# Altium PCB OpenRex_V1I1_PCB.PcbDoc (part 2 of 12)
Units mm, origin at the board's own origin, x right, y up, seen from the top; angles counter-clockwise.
Board outline 70 x 95 mm, 10 copper layers (L1, L2, L3, L4 (PWR), L5 (PWR), L6 (PWR), L7 (PWR), L8, L9, L10), stack 1.632 mm thick; 1080 components, 708 nets, 3831 pads, 2373 vias.
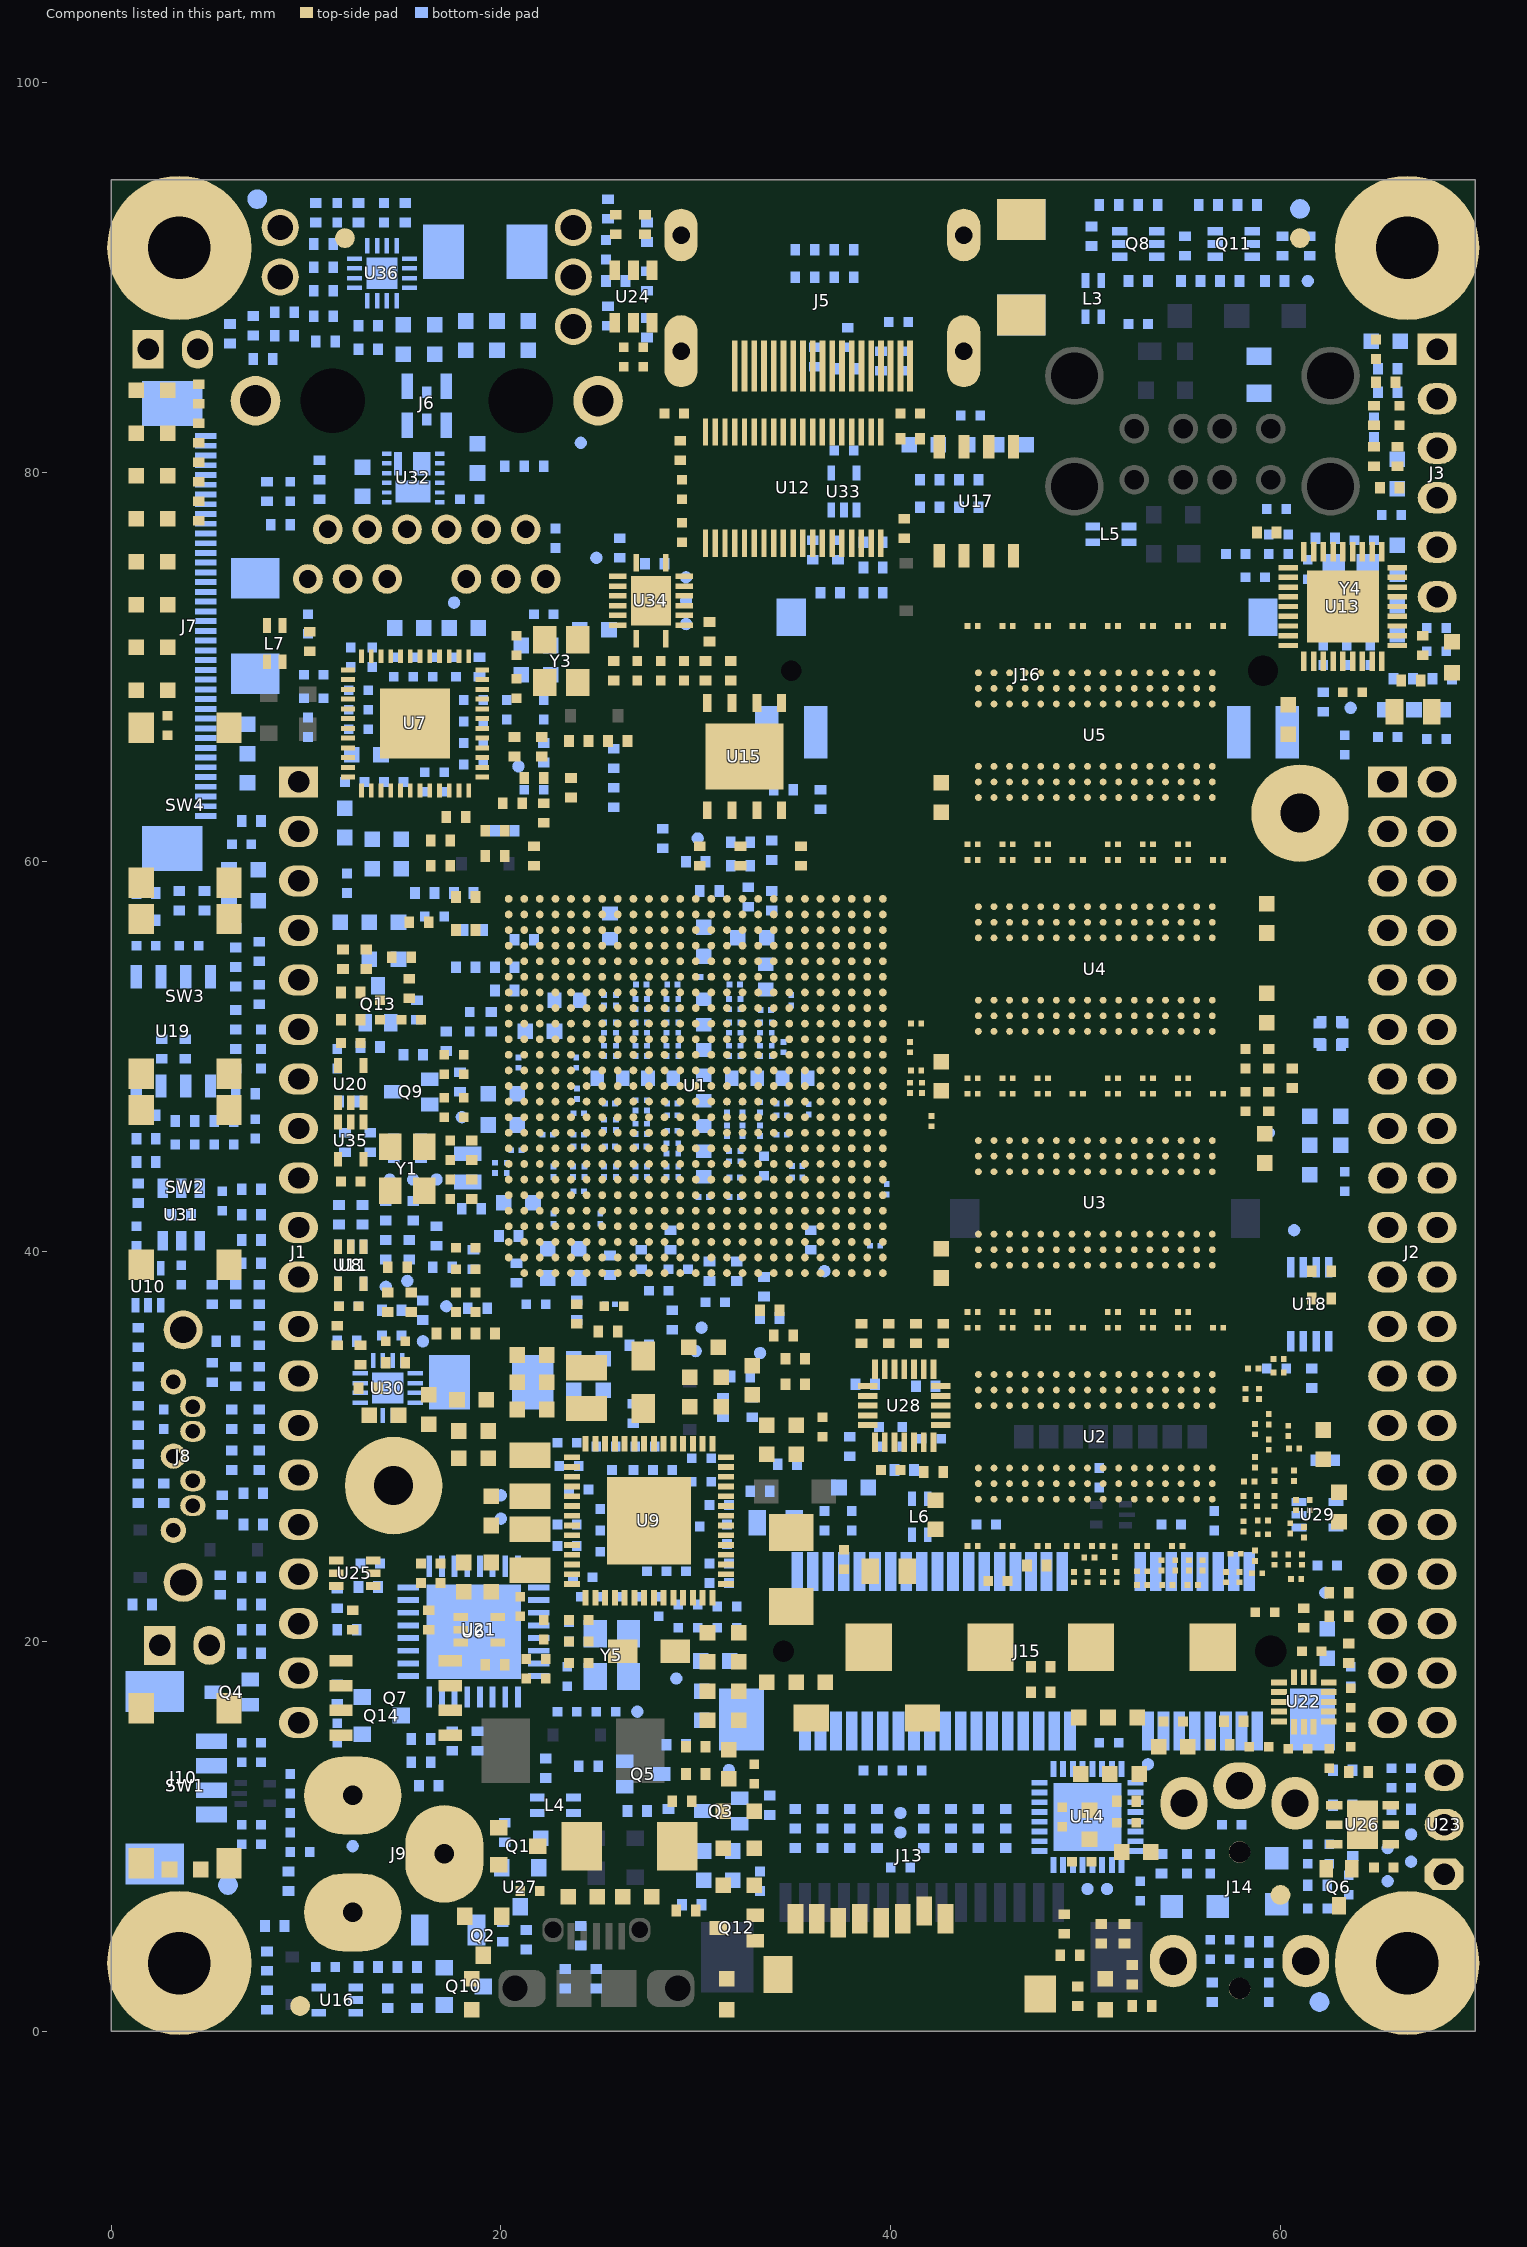
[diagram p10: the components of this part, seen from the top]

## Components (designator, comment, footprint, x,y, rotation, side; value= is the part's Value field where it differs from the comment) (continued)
L7 "ACM2012-900-2P-T002" ACM2012 8.4,71.2 r90 top
L8 "1u / 2.6A" IFSC_79MILX98MIL 24.4,33 r270 top
L9 "1u / 2.6A" IFSC_79MILX98MIL 21.5,28.5 r90 top
L10 "1u / 2.6A" IFSC_79MILX98MIL 21.5,24.7 r270 top
L11 "2u2 / 2.75A" IHLP_160MILX175MIL 34.9,23.7 r90 top
L12 "1u" IHLP_204MILX216MIL 19.5,33.3 r0 bottom locked
L13 "1u" IHLP_204MILX216MIL 19.2,91.3 r0 bottom
MH1 "MH_7.4MMC_3.2MMD" MH_7.4MMD_3.2MMD 3.5,3.5 r0 top locked
MH2 "MH_7.4MMC_3.2MMD" MH_7.4MMD_3.2MMD 66.5,3.5 r0 top locked
MH3 "MH_7.4MMC_3.2MMD" MH_7.4MMD_3.2MMD 66.5,91.5 r0 top locked
MH4 "MH_7.4MMC_3.2MMD" MH_7.4MMD_3.2MMD 3.5,91.5 r0 top locked
MH5 "MH_5MMC_2MMD" MH_5MMD_2MMD 14.5,28 r0 top locked
MH6 "MH_5MMC_2MMD" MH_5MMD_2MMD 61,62.5 r0 top locked
Q1 "DMP2035U-7" SOT-23-3-123 20.9,9.5 r0 top
Q2 "DMP2035U-7" SOT-23-3-123 19.1,4.9 r270 top
Q3 "2N7002BKW,115" SC70_SOT323 31.3,11.3 r180 bottom
Q4 "2N7002BKW,115" SC70_SOT323 6.2,17.4 r180 bottom
Q5 "2N7002BKW,115" SC70_SOT323 27.3,13.2 r0 bottom
Q6 "2N7002BKW,115" SC70_SOT323 63,7.4 r270 top
Q7 "SI4425BDY-T1-E3" 8_SOIC_3.9MM 14.6,17.1 r0 top
Q8 "2N7002BKS,115" SOT363 52.7,91.7 r0 bottom
Q9 "2N7002BKW,115" SC70_SOT323 15.4,48.2 r180 bottom
Q10 "MMBT3906,215" SOT-23-3-123 18.1,2.3 r0 bottom
Q11 "2N7002BKS,115" SOT363 57.6,91.7 r0 bottom
Q12 "2N7002BKW,115" SC70_SOT323 32.1,5.3 r180 top
Q13 "2N7002BKW,115" SC70_SOT323 13.7,52.7 r90 bottom
Q14 "MMBT3906,215" SOT-23-3-123 13.9,16.2 r0 bottom
R1 "47R" R0201 60.4,24.2 r270 top
R2 "47R" R0201 57.9,23.3 r90 top
R3 "47R" R0201 60.7,28.5 r270 top
R4 "240R" R0201 49.6,36.1 r0 top
R5 "240R" R0201 49.6,48.1 r0 top
R6 "10k" R0201 35.8,47.3 r90 bottom
R7 "10k" R0201 39.8,43.2 r270 bottom
R8 "240R" R0201 49.6,60.1 r0 top
R9 "240R" R0201 49.6,72.1 r0 top
R10 "240R" R0201 41.3,51.7 r0 top
R11 "47R" R0201 56,23.9 r270 top
R12 "47R" R0201 59.7,28.5 r270 top
R13 "0R" R0402 23.9,37 r90 bottom
R14 "0R" R0402 20.4,40.8 r0 bottom
R15 "10k" R0402 32.3,61 r0 bottom
R16 "49R9" R0402 19.2,35.8 r180 top
R17 "49R9" R0402 17.2,35.8 r0 top
R18 "0R" R0402 25.6,39.3 r90 bottom
R19 "0R" R0402 19.5,51.8 r270 bottom
R20 "2M2" R0402 18.5,45.2 r90 top
R21 "47k" R0402 39.1,73.8 r0 bottom
R22 "47R" R0201 59.7,24.2 r270 top
R23 "1k6" R0402 36,76 r90 bottom
R24 "0R" R0402 25.5,35.9 r0 top
R25 "0R" R0402 35.1,33.2 r180 top
R26 "0R" R0402 23.9,36.8 r270 top
R27 "0R" R0402 28.7,40.6 r90 bottom
R28 "4k99" R0402 37.9,30 r270 bottom
R29 "0R" R0402 30.7,39 r90 bottom
R30 "1k" R0402 20.7,65.9 r90 top
R31 "47R" R0201 59.1,26.2 r180 top
R32 "1k6" R0201 25.6,37.3 r0 bottom
R33 "0R" R0402 39.3,9.9 r90 bottom
R34 "47R" R0201 52.9,23.6 r0 top
R35 "22R" R0402 21.2,56 r180 bottom
R36 "0R" R0402 35.9,40.6 r90 bottom
R37 "200R" R0402 20.8,38.9 r90 bottom
R38 "47R" R0201 58.7,24.4 r270 top
R39 "47R" R0201 57.2,23.3 r90 top
R40 "47R" R0201 61.2,25.6 r90 top
R41 "0R" R0402 2.6,50.4 r270 bottom
R42 "47R" R0201 52.9,22.9 r0 top
R43 "22R" R0402 21.7,60.3 r90 top
R44 "47R" R0201 59.7,27.2 r90 top
R45 "47R" R0201 51.5,24.6 r270 top
R46 "0R" R0402 29.2,81.1 r90 top
R47 "15k" R0402 41,81.7 r180 top
R48 "10k" R0402 13.3,45.6 r90 bottom
R49 "10k" R0402 15.4,37.4 r270 top
R50 "47R" R0201 59.4,31.4 r270 top
R51 "0R" R0402 14.7,39.2 r180 top
R52 "10k" R0402 48.9,5.5 r270 top
R53 "10k" R0402 49.2,3.9 r180 top
R54 "10k" R0402 50.8,5 r90 top
R55 "4k99" R0201 24,47.1 r0 bottom
R56 "4k99" R0201 22.4,46 r0 bottom
R57 "10k" R0402 32.3,59.8 r180 bottom
R58 "10k" R0402 15.9,45.3 r270 bottom
R59 "10k" R0402 1.4,33.6 r90 bottom
R60 "0R" R0402 51.2,93.7 r180 bottom
R61 "1k" R0201 25.1,41.7 r90 bottom
R62 "10k" R0402 16,37 r270 bottom
R63 "10k" R0402 18.6,39.6 r270 bottom
R64 "10k" R0402 17,39.2 r0 bottom
R65 "0R" R0402 39.3,10.9 r270 bottom
R66 "47R" R0201 59.1,25.5 r180 top
R67 "0R" R0402 47.7,18.7 r180 top
R68 "10k" R0402 11.7,41.9 r90 bottom
R69 "10k" R0402 12.9,41.9 r90 bottom
R70 "0R" R0402 14.2,37.4 r90 top
R71 "0R" R0402 37.9,9.9 r90 bottom
R72 "47R" R0201 58.7,30.9 r270 top
R73 "100k" R0402 7.3,26 r180 bottom
R74 "0R" R0402 33.9,58 r90 bottom
R75 "10k" R0402 24,66.2 r180 top
R76 "0R" R0402 32.1,39 r270 bottom
R77 "47R" R0201 51.6,23.3 r90 top
R78 "0R" R0402 27.2,39.6 r270 bottom
R79 "47R" R0201 59.9,33.8 r180 top
R80 "0R" R0402 18.6,56.5 r180 bottom
R81 "220R" R0402 8,79 r90 bottom
R82 "220R" R0402 25.9,89.8 r0 bottom
R83 "22R" R0402 19.7,61.6 r180 top
R84 "12k1" R0402 18.9,70 r270 bottom
R85 "22R" R0402 20.6,63 r180 top
R86 "22R" R0402 21.7,64.3 r180 top
R87 "4k99" R0402 22.2,62.5 r90 top
R88 "0R" R0402 34.5,63.7 r180 bottom
R89 "4k99" R0402 22.2,65.6 r90 bottom
R90 "22R" R0402 16.7,40.8 r90 bottom
R91 "10k" R0402 18.2,56.5 r180 top
R92 "22R" R0402 18.8,37.1 r180 bottom
R93 "0R" R0402 14.1,42.1 r270 bottom
R94 "10k" R0402 10.2,71.3 r270 top
R95 "10k" R0402 19.7,60.3 r180 top
R96 "10k" R0402 16.9,59.8 r180 top
R97 "10k" R0402 18.2,58.2 r180 top
R98 "10k" R0402 16.9,61.1 r180 top
R99 "191R" R0201 20.9,49.7 r270 bottom
R100 "1k, 1206, 0.5W" R1206 17.3,5.2 r180 bottom
R101 "1k" R0402 17.7,62.3 r0 top
R102 "1k" R0402 8.7,77.3 r180 bottom
R103 "47R" R0201 55.3,23.9 r270 top
R104 "0R" R0402 47.7,17.4 r0 top
R105 "47R" R0201 60.7,29.9 r180 top
R106 "47R" R0201 60.5,25.8 r90 top
R107 "47R" R0201 58.9,32.7 r90 top
R108 "47R" R0201 59.9,34.5 r180 top
R109 "10k" R0402 31.8,69.8 r270 top
R110 "10k" R0402 61.2,21.2 r270 top
R111 "47R" R0201 58.1,25.9 r90 top
R112 "49R9" R0201 50.1,23.3 r270 top
R113 "49R9" R0201 41.6,48.4 r90 top
R114 "10k" R0402 62.1,37.6 r0 top
R115 "10k" R0402 62.1,39 r0 top
R116 "10k" R0402 33.8,36.6 r0 bottom
R117 "0R" R0402 3.8,50.4 r270 bottom
R118 "47k" R0402 39.1,75.1 r0 bottom
R119 "0R" R0402 37.9,10.9 r270 bottom
R120 "0R" R0402 36.5,9.9 r90 bottom
R121 "0R" R0402 36.5,10.9 r270 bottom
R122 "0R" R0402 35.1,9.9 r90 bottom
R123 "0R" R0402 35.1,10.9 r270 bottom
R124 "22R" R0402 28.8,36.5 r270 bottom
R125 "0R" R0402 43.1,9.9 r90 bottom
R126 "0R" R0402 43.1,10.9 r270 bottom
R127 "0R" R0402 41.7,9.9 r90 bottom
R128 "0R" R0402 41.7,10.9 r270 bottom
R129 "0R" R0402 45.9,9.9 r90 bottom
R130 "22R" R0402 35.4,60.3 r90 top
R131 "22R" R0402 30.2,60.3 r90 top
R132 "4k99" R0402 38.7,33.2 r180 bottom
R133 "4k99" R0402 27.5,87.4 r90 bottom
R134 "4k99" R0402 27.5,89.8 r270 bottom
R135 "0R" R0402 45.9,10.9 r270 bottom
R136 "0R" R0402 44.5,9.9 r90 bottom
R137 "4k99" R0402 8.9,88.2 r180 bottom
R138 "0R" R0402 44.5,10.9 r270 bottom
R139 "0R" R0402 34.5,35.7 r180 top
R140 "10k" R0402 2.7,27.6 r90 bottom
R141 "33R" R0402 1.4,29.6 r270 bottom
R142 "4k99" R0402 7.3,87.5 r90 bottom
R143 "10k" R0402 18.2,54.6 r180 bottom
R144 "10k" R0402 11.6,35.7 r90 top
R145 "1k5" R0402 4.5,84 r90 top
R146 "240R" R0402 29.5,6.2 r0 top
R147 "10k" R0402 16.1,58.4 r180 bottom
R148 "4k99" R0402 5.2,33.8 r90 bottom
R149 "33R" R0402 18.1,58.4 r180 bottom
R150 "10k" R0402 29.8,6.5 r0 bottom
R151 "10k" R0402 33.8,37 r180 top
R152 "22R" R0402 20.2,53.4 r180 bottom
R153 "22R" R0402 20.2,54.6 r180 bottom
R154 "0R" R0402 52.4,2.9 r270 top
R155 "0R" R0402 13.2,3.3 r180 bottom
R156 "0R" R0402 52,5 r270 top
R157 "4k99" R0402 36.9,73.8 r0 bottom
R158 "0R" R0402 14.1,40.1 r90 bottom
R159 "10k" R0402 32.7,58.2 r90 bottom
R160 "6k04" R0201 22.7,41.7 r270 bottom
R161 "22R" R0402 18.5,42.2 r180 bottom
R162 "1k" R0402 23.6,63.8 r270 top
R163 "10k" R0402 33.9,60.6 r270 bottom
R164 "10k" R0402 30.7,58.5 r0 bottom
R165 "1k5" R0402 4.5,82 r270 top
R166 "10k" R0402 30,60 r0 bottom
R167 "10M" R0402 18.5,43.2 r270 top
R168 "10M" R0201 19.7,44.3 r90 bottom
R169 "0R" R0402 64.8,80.8 r90 top
R170 "0R" R0402 47.5,23.9 r180 top
R171 "4k99" R0402 17.2,50.8 r90 bottom
R172 "4k99" R0402 14.5,45.3 r90 bottom
R173 "10k" R0402 15.5,50.1 r0 bottom
R174 "10k" R0402 8,1.6 r90 bottom
R175 "10k" R0402 17.9,48.7 r90 bottom
R176 "1k5" R0402 4.5,80 r270 top
R177 "0R" R0402 5.2,37.8 r270 bottom
R178 "0R" R0402 25.8,65.3 r90 bottom
R179 "0R" R0402 25.8,63.3 r270 bottom
R180 "0R" R0402 26,66.2 r0 top
R181 "22R" R0402 22.1,65.9 r270 top
R182 "0R" R0402 37.8,86.9 r270 bottom
R183 "0R" R0402 37.8,85.3 r180 bottom
R184 "0R" R0402 39.5,85.7 r270 bottom
R185 "240R" R0402 49.6,1.8 r270 top
R186 "240R" R0402 24.9,2.7 r90 bottom
R187 "4k99" R0402 40.8,85.7 r90 bottom
R188 "4k99" R0402 36.1,85.9 r90 bottom
R189 "1k5" R0402 4.5,78 r90 top
R190 "27k" R0402 40.7,77.1 r90 top
R191 "10k" R0402 52.9,1.3 r180 top
R192 "1k5" R0402 15.3,53.5 r270 top
R193 "1k5" R0402 14.9,55.1 r0 top
R194 "0R" R0402 16.7,82.7 r180 bottom
R195 "0R" R0402 8.9,87 r0 bottom
R196 "0R" R0402 6.1,87.1 r90 bottom
R197 "10k" R0402 35.1,34.5 r0 top
R198 "10k" R0402 24.1,4.9 r90 bottom
R199 "10k" R0402 23.3,2.7 r90 bottom
R200 "1k5" R0402 4.8,58 r270 bottom
R201 "10k" R0402 33.8,11.6 r270 bottom
R202 "1k5" R0402 3.5,58 r270 bottom
R203 "100k" R0402 7.2,19.4 r180 bottom
R204 "0R" R0402 28.6,10.9 r270 bottom
R205 "4k99" R0402 6.2,31.4 r270 bottom
R206 "22R" R0402 33.5,38.2 r270 bottom
R207 "0R" R0402 15.7,82.7 r180 bottom
R208 "10k" R0402 7.2,40.6 r180 bottom
R209 "10k" R0402 5.9,35.4 r180 bottom
R210 "10k" R0402 7.2,41.9 r0 bottom
R211 "10k" R0402 6.4,33.6 r90 bottom
R212 "10k" R0402 15.8,56.9 r180 top
R213 "10k" R0402 27,11.3 r180 bottom
R214 "100k" R0402 8,3.6 r90 bottom
R215 "100k" R0402 66,80.8 r270 top
R216 "100k" R0402 65.6,79.2 r180 top
R217 "100k" R0402 64.8,82.9 r270 top
R218 "0R" R0402 65.4,84.6 r180 top
R219 "1k" R0402 65.5,84.1 r180 bottom
R220 "100k" R0402 60.1,91.6 r270 bottom
R221 "100k" R0402 61.5,91.6 r270 bottom
R222 "12k" R0402 59.3,76.9 r180 top
R223 "100k" R0402 65.5,85.3 r180 bottom
R224 "100k" R0402 68.3,69.4 r180 bottom
R225 "10k" R0402 15.3,40.1 r90 bottom
R226 "240R" R0402 66.2,11.4 r0 bottom
R227 "0R" R0402 7.2,43.2 r180 bottom
R228 "0R" R0402 7.6,33.6 r90 bottom
R229 "10k" R0402 6.4,37.8 r270 bottom
R230 "15k" R0402 61.9,7.5 r0 bottom
R231 "15k" R0402 58.9,4.6 r180 bottom
R232 "33R" R0402 63.7,9.5 r270 bottom
R233 "33R" R0402 56.5,2 r90 bottom
R234 "0R" R0402 52.1,11.8 r180 top
R235 "2k2" R0402 53.9,8.6 r90 bottom
R236 "0R" R0402 31.4,32 r270 bottom
R237 "47k" R0402 24.5,13.6 r180 bottom
R238 "0R" R0402 63.2,13.4 r180 bottom
R239 "100k" R0402 7.2,21.9 r0 bottom
R240 "10k" R0402 28.3,61.2 r270 bottom
R241 "0R" R0402 57.6,15.9 r180 top
R242 "0R" R0402 56.9,14.7 r180 top
R243 "0R" R0402 64,13.3 r180 top
R244 "10k" R0402 32.3,60.3 r90 top
R245 "240R" R0402 59.4,49.9 r90 top
R246 "60R4" R0402 3.8,46.7 r0 bottom
R247 "0R" R0402 63.2,11.6 r180 bottom
R248 "0R" R0402 6.9,48.1 r0 bottom
R249 "60R4" R0402 5.8,46.7 r0 bottom
R250 "10k" R0402 1.8,47 r0 bottom
R251 "10k" R0402 12.3,53.3 r0 top
R252 "10k" R0402 11.9,55 r270 top
R253 "49R9" R0201 49.4,23.3 r270 top
R254 "33R" R0402 12.3,51.9 r180 top
R255 "33R" R0402 13.1,55 r90 top
R256 "49R9" R0201 41,48.4 r90 top
R257 "4k99" R0402 27.4,92.7 r90 top
R258 "0R" R0402 27.5,92.3 r270 bottom
R259 "0R" R0402 25.9,92.7 r270 top
R260 "100k" R0201 32,42.8 r180 bottom
R261 "100k" R0402 33.3,27.7 r180 bottom
R262 "100k" R0402 5.6,22.9 r270 bottom
R263 "47k" R0402 32.9,32 r90 bottom
R264 "47k" R0402 32.3,33.6 r0 bottom
R265 "10k" R0402 34.7,29.1 r180 bottom
R266 "100k" R0402 27.1,35.2 r0 bottom
R267 "330R" R0402 30,14.6 r0 top
R268 "330R" R0402 30,13.2 r180 top
R269 "330R" R0402 29.3,11.8 r0 top
R270 "10k" R0402 19.7,18.8 r0 top
R271 "0R" R0402 15.5,42.1 r270 bottom
R272 "10k" R0402 1.4,35.6 r270 bottom
R273 "0R" R0402 7.6,31.4 r90 bottom
R274 "240R" R0402 59.4,47.7 r90 top
R275 "22R" R0402 7.2,62.1 r180 bottom
R276 "0R" R0402 6.4,54.1 r90 bottom
R277 "0R" R0402 7.6,55.4 r270 bottom
R278 "0R" R0402 6.4,49.9 r90 bottom
R279 "0R" R0402 6.4,51.9 r270 bottom
R280 "10k" R0402 13.3,50.5 r180 bottom
R281 "0R" R0402 16.3,21.1 r270 top
R282 "0R" R0402 13.2,22.8 r180 bottom
R283 "10k" R0402 66.7,69.3 r180 top
R284 "10k" R0402 67.3,71.1 r90 top
R285 "10k" R0402 62.2,68.2 r270 bottom
R286 "10k" R0402 66.3,69.4 r0 bottom
R287 "0R" R0402 25.5,88 r90 bottom
R288 "0R" R0402 25.5,93.5 r270 bottom
R289 "10k" R0402 12.4,21.1 r90 top
R290 "4k99" R0402 6.4,56.1 r90 bottom
R291 "4k99" R0402 7.6,53.2 r90 bottom
R292 "11k8" R0402 20.2,10.2 r90 bottom
R293 "10k" R0402 15.7,1.7 r270 bottom
R294 "0R" R0805_SMALL 16.2,82.4 r180 bottom
R295 "0R" R0805_SMALL 16.2,84.4 r0 bottom
R296 "10k5" R0402 21.3,4.7 r90 bottom
R297 "0R" R0402 16.7,84.1 r180 bottom
R298 "0R" R0402 15.7,84.1 r180 bottom
R299 "33R" R0402 18.8,14.9 r270 bottom
R300 "33R" R0402 17.5,14.9 r270 bottom
R301 "470k" R0402 20.1,5.1 r270 bottom
R302 "4k99" R0402 1.4,43 r270 bottom
R303 "10k" R0402 1.8,44.6 r0 bottom
R304 "0R" R0402 15.2,3.3 r0 bottom
R305 "10k" R0402 14.2,1.7 r90 bottom
R306 "240R" R0201 51.4,36.1 r0 top
R307 "240R" R0201 51.4,48.1 r0 top
R308 "240R" R0201 51.4,60.1 r0 top
R309 "240R" R0201 51.4,72.1 r0 top
R310 "10k" R0402 62.3,29.3 r180 bottom
R311 "0R" R0402 63.5,19.4 r90 top
R312 "10k" R0402 42.7,35.8 r270 top
R313 "0R" R0402 41.3,35.8 r90 top
R314 "0R" R0402 39.9,35.8 r90 top
R315 "10k" R0402 63,21.3 r180 top
R316 "0R" R0402 63,22.5 r180 top
R317 "10k" R0402 42.2,28.7 r180 top
R318 "0R" R0402 61.6,33.5 r270 bottom
R319 "10k" R0402 25.8,69.8 r90 top
R320 "0R" R0402 40.7,28.8 r0 bottom
R321 "0R" R0402 44,79.6 r0 bottom
R322 "0R" R0402 43,79.6 r180 bottom
R323 "0R" R0402 42,79.6 r0 bottom
R324 "0R" R0402 44,78.2 r0 bottom
R325 "0R" R0402 43,78.2 r180 bottom
R326 "0R" R0402 42,78.2 r0 bottom
R327 "0R" R0402 35.6,91.4 r180 bottom
R328 "0R" R0402 36.6,91.4 r0 bottom
R329 "0R" R0402 37.6,91.4 r180 bottom
R330 "0R" R0402 35.6,90 r180 bottom
R331 "0R" R0402 36.6,90 r0 bottom
R332 "0R" R0402 37.6,90 r180 bottom
R333 "0R" R0402 7.6,37.8 r270 bottom
R334 "0R" R0402 6.2,29.3 r270 bottom
R335 "10k" R0402 5.7,27 r270 bottom
R336 "82k" R0402 14.6,34.3 r0 top
R337 "150k" R0402 7.6,29.3 r90 bottom
R338 "100k" R0402 7.3,27.6 r180 bottom
R339 "63k4" R0402 12.8,34.7 r90 top
R340 "0R" R0402 26.8,31.7 r90 bottom
R341 "0R" R0402 21.3,29.8 r0 bottom
R342 "0R" R0402 13.2,33 r180 top
R343 "0R" R0402 12.1,35.4 r0 bottom
R344 "100k" R0402 14.4,37 r0 bottom
R345 "0R" R0402 60.6,48.9 r270 top
R346 "1k" R0402 36.4,63.2 r270 bottom
R347 "100k" R0402 1.4,27.6 r270 bottom
R348 "0R" R0402 1.4,31.6 r90 bottom
R350 "0R" R0402 3.6,41.9 r180 bottom
R351 "0R" R0402 7.6,35.7 r90 bottom
R352 "0R" R0402 20.7,80.3 r0 bottom
R353 "0R" R0402 21.7,80.3 r0 bottom
R354 "0R" R0402 10.7,79.1 r90 bottom
R355 "0R" R0402 10.7,80.1 r270 bottom
R356 "47k" R0402 39.1,76.4 r0 bottom
R357 "0R" R0402 37.3,76 r270 bottom
R358 "1M" R0402 62.3,76.6 r180 bottom
R359 "10k" R0402 30.7,71.8 r270 top
R360 "10k" R0402 30.5,69.8 r270 top
R361 "0R" R0402 27.9,72.5 r0 bottom
R362 "0R" R0402 27.9,73.7 r0 bottom
R363 "0R" R0402 26.1,76.1 r270 bottom
R364 "0R" R0402 27.9,75.3 r0 bottom
R365 "100k" R0402 7.2,20.6 r180 bottom
R366 "0R" R0402 63.2,51.2 r90 bottom
R367 "0R" R0402 62.6,50.6 r180 bottom
R368 "0R" R0402 62.6,51.8 r0 bottom
R369 "0R" R0402 62,51.2 r270 bottom
R370 "3k3" R0402 50.3,92.1 r90 bottom
R371 "3k3" R0402 58.3,93.7 r0 bottom
R372 "3k3" R0402 55.1,91.6 r270 bottom
R373 "0R" R0402 52.7,89.8 r0 bottom
R374 "0R" R0402 56.3,93.7 r180 bottom
R375 "3k3" R0402 53.2,93.7 r0 bottom
R376 "3k3" R0402 55.4,89.8 r180 bottom
R377 "3k3" R0402 59.7,89.8 r0 bottom
R378 "0R" R0402 57.4,89.8 r0 bottom
R379 "240R" R0402 8.4,5.4 r0 bottom
R380 "10k" R0402 7.2,23.3 r0 bottom
R381 "10k" R0402 20.2,61.6 r0 bottom
R382 "10k" R0402 1.8,45.8 r180 bottom
R383 "10k" R0402 41.8,33.1 r0 bottom
R384 "0R" R0402 24.1,31.6 r0 bottom
R385 "100k" R0402 29,14.7 r0 bottom
R386 "24k" R0402 15.9,15 r180 bottom
R387 "1k5" R0402 16.3,12.6 r0 bottom
R388 "3k" R0402 15.9,13.8 r180 bottom
R389 "0R" R0402 1.6,21.9 r0 bottom
R390 "0R" R0402 1.8,57 r0 bottom
R391 "0R" R0402 22.3,13.5 r270 bottom
R392 "0R" R0402 1.8,58.4 r0 bottom
R393 "100k" R0402 9.1,7.7 r90 bottom
R394 "100k" R0402 12.1,20.6 r180 bottom
R395 "100k" R0402 11.6,22.2 r270 bottom
R396 "100k" R0402 11.6,17.3 r270 bottom
R397 "0R" R0402 10.9,89.3 r180 bottom
R398 "10k" R0402 13.2,87.5 r180 bottom
R399 "390k" R0402 15.1,93.3 r90 bottom
R400 "150k" R0402 10.9,88 r0 bottom
R401 "100k" R0402 13.2,86.3 r0 bottom
R402 "86k6" R0402 12.7,93.3 r270 bottom
R403 "47k" R0402 11,86.7 r180 bottom
R404 "0R" R0402 7.8,85.8 r180 bottom
R405 "10k" R0402 7.2,39.4 r0 bottom
R406 "0R" R0402 10.9,90.5 r0 bottom
R407 "0R" R0402 10.9,91.7 r0 bottom
R408 "100k" R0402 10.5,93.3 r90 bottom
R410 "10k" R0402 38.5,35.8 r270 top
R411 "0R" R0402 12,45.6 r270 bottom
R412 "0R" R0402 12.2,47.7 r180 bottom
R413 "0R" R0402 15.7,52.4 r90 bottom
SW1 "PTS645SH50SMTR92 LFS" TACT_SMD 3.8,12.6 r270 top
SW2 "PTS645SH50SMTR92 LFS" TACT_SMD 3.8,43.3 r270 top
SW3 "PTS645SH50SMTR92 LFS" TACT_SMD 3.8,53.1 r270 top locked
SW4 "PTS645SH50SMTR92 LFS" TACT_SMD 3.8,62.9 r270 top locked
TP1 "TP_25MILC" TP_25C 14.1,38.2 r90 bottom
TP2 "TP_25MILC" TP_25C 15.5,43.7 r90 bottom
TP3 "TP_25MILC" TP_25C 14.3,43.7 r90 bottom
TP4 "TP_25MILC" TP_25C 23.55,8.6 r90 bottom
TP5 "TP_25MILC" TP_25C 15.2,38.5 r90 bottom
TP6 "TP_25MILC" TP_25C 66.7,10.1 r270 bottom
TP7 "TP_25MILC" TP_25C 50.1,7.3 r90 bottom
TP8 "TP_25MILC" TP_25C 30,34.9 r270 bottom
TP9 "TP_25MILC" TP_25C 17.6,73.3 r90 bottom
TP10 "TP_25MILC" TP_25C 31.7,13.4 r270 bottom
TP11 "TP_25MILC" TP_25C 16,35.4 r270 bottom
TP12 "TP_25MILC" TP_25C 17.2,37.2 r90 bottom
TP13 "TP_25MILC" TP_25C 16.7,43.7 r90 bottom
TP14 "TP_25MILC" TP_25C 62.3,22.5 r90 bottom
TP15 "TP_25MILC" TP_25C 60.7,41.1 r270 bottom
TP16 "TP_25MILC" TP_25C 63.6,67.9 r90 bottom
TP17 "TP_25MILC" TP_25C 65.5,7.7 r270 bottom
TP18 "TP_25MILC" TP_25C 65.5,9.4 r270 bottom
TP19 "TP_25MILC" TP_25C 40.5,11.2 r90 bottom
TP20 "TP_25MILC" TP_25C 40.5,10.2 r90 bottom
TP21 "TP_25MILC" TP_25C 66.7,8.7 r270 bottom
TP22 "TP_25MILC" TP_25C 29.5,73.4 r90 bottom
TP23 "TP_25MILC" TP_25C 24.9,75.6 r90 bottom
TP24 "TP_25MILC" TP_25C 29.5,72.2 r90 bottom
TP25 "TP_25MILC" TP_25C 29.5,74.6 r90 bottom
TP26 "TP_25MILC" TP_25C 18,46.9 r90 bottom
TP27 "TP_25MILC" TP_25C 20.9,64.9 r90 bottom
TP28 "TP_25MILC" TP_25C 30.1,61.2 r90 bottom
TP29 "TP_25MILC" TP_25C 20,26.3 r90 bottom
TP30 "TP_25MILC" TP_25C 20,27.5 r90 bottom
TP31 "TP_25MILC" TP_25C 30.3,36.1 r90 bottom
TP32 "TP_25MILC" TP_25C 59.4,46.1 r90 bottom
TP33 "TP_25MILC" TP_25C 24.1,81.5 r90 bottom
TP34 "TP_25MILC" TP_25C 53.2,13.7 r90 bottom
TP35 "TP_25MILC" TP_25C 36.6,39 r90 bottom
TP36 "TP_25MILC" TP_25C 27,16.4 r90 bottom
TP37 "TP_25MILC" TP_25C 33.3,34.8 r90 bottom
TP38 "TP_25MILC" TP_25C 29,18.1 r180 bottom
TP39 "TP_25MILC" TP_25C 12.4,9.5 r90 bottom
TP40 "TP_25MILC" TP_25C 61.4,89.8 r90 bottom
TP41 "TP_25MILC" TP_25C 51.1,7.3 r90 bottom
U1 "MCIMX6Q5EYM10AC_v.ORX" PBGA624 30,48.5 r90 top locked
U2 "MT41J256M16HA-125:E" 96_FPGA_DD3_14MMX10MM-SMALL_SIZE 50.5,30.5 r90 top locked
U3 "MT41J256M16HA-125:E" 96_FPGA_DD3_14MMX10MM-SMALL_SIZE 50.5,42.5 r90 top locked
U4 "MT41J256M16HA-125:E" 96_FPGA_DD3_14MMX10MM-SMALL_SIZE 50.5,54.5 r90 top locked
U5 "MT41J256M16HA-125:E" 96_FPGA_DD3_14MMX10MM-SMALL_SIZE 50.5,66.5 r90 top locked
U6 "LPC1345FHN33,551-ND" HVQFN33_7X7MM 18.6,20.5 r180 bottom
U7 "KSZ9031RNXIA" QFN48_SMALL_EP_7MMX7MM 15.6,67.1 r270 top locked
U8 "SN74AHC1G09DCKR" SC70_5 12.3,39.3 r270 bottom
U9 "MMPF0100NPAEP" "56-VFQFN EP" 27.6,26.2 r270 top locked
U10 "SN74AHC1G09DCKR" SC70_5 1.9,38.2 r90 bottom
U11 "SN74LVC1G08DCKR" SC70_5 12.3,39.3 r270 top
U12 "CM2020-00TR" TSSOP_38 35,79.2 r90 top locked
U13 "USB2514BI-AEZG" QFN36_6MMX6MM 63.2,73.1 r0 top locked
U14 "SGTL5000XNAA3R2" "QFN32 5x5x0.85_V1.1" 50.1,11 r180 bottom
U15 "SST26VF032B-104I/MF" WSON8_6X5MM 32.5,65.4 r90 top
U16 "M74VHC1GT126DF1G" SC70_5 11.6,1.6 r180 bottom
U17 "MIC2026-1YM TR" 8_SOIC_3.9MM 44.4,78.5 r90 top locked
U18 "BR24L02FVM-WTR" "MSOP8 _SMALLER" 61.5,37.3 r270 bottom
U19 "TJA1040T" 8_SOIC_3.9MM 3.2,51.3 r270 bottom
U20 "SN74LVC1G08DCKR" SC70_5 12.3,48.6 r90 top
U21 "SN74AHC1G09DCKR" SC70_5 18.9,20.6 r0 top
U22 "FXOS8700CQR1" QFN16_3X3MM 61.2,16.9 r180 top locked
U23 "TSOP38238" TSOP382 68.4,8.06 r180 top locked
U24 "TMP101NA" SOT23-6_DBV6 26.8,89 r270 top
U25 "TS5A3157DCKR" SC70_6 12.5,23.5 r0 top
U26 "SHT21" 6_DFN_3MMX3MM 64.2,10.6 r0 top
U27 "TL431AQDBZR" SOT-23-3-123 21,7.4 r270 bottom
U28 "FXAS21002CQR1" QFN24_4X4MM 40.7,32.1 r270 top
U29 "SN74LVC1G14DCKR" SC70_5 61.9,26.5 r0 bottom
U30 "ISL8024AIRTAJZ-T7A" 16-TQFN_3mmx3mm_V1.1 14.2,33 r90 bottom
U31 "TPS3808G09DBVRG4" DBV_SOT_23_6 3.6,41.9 r90 bottom
U32 "MIC33050-4YHL TR" MLF_3X3_12PINS 15.5,79.7 r0 bottom
U33 "SN74LVC1G17DCKR" SC70_5 37.6,79 r90 bottom
U34 "SN74AVC4T245RGYR" "RGY (R-PVQFN-N16)" 27.7,73.4 r90 top
U35 "SN74LVC1G08DCKR" SC70_5 12.3,45.7 r270 top
U36 "ISL8024AIRTAJZ-T7A" 16-TQFN_3mmx3mm_V1.1 13.9,90.2 r90 bottom
Y1 "24MHz" ABM8 15.2,44.25 r90 top
Y2 "32.768kHz" ABS06 18.3,44.3 r90 bottom
Y3 "25.000MHz" ABM8G 23.1,70.3 r90 top
Y4 "24MHz" ABM8 63.6,74 r270 bottom
Y5 "7M-12.000MAHE-T" 7M 25.7,19.3 r270 bottom

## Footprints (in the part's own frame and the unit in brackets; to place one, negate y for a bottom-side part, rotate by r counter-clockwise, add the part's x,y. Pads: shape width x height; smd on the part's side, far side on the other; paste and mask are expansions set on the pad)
4-1734592-0 [mm] "Creator MM"
  rect 0.3x1.1 smd mask+0.025: 1(-9.75,0.85) 2(-9.25,0.85) 3(-8.75,0.85) 4(-8.25,0.85) 5(-7.75,0.85) 6(-7.25,0.85) 7(-6.75,0.85) 8(-6.25,0.85) 9(-5.75,0.85) 10(-5.25,0.85) 11(-4.75,0.85) 12(-4.25,0.85) 13(-3.75,0.85) 14(-3.25,0.85) 15(-2.75,0.85) 16(-2.25,0.85) 17(-1.75,0.85) 18(-1.25,0.85) 19(-0.75,0.85) 20(-0.25,0.85) 21(0.25,0.85) 22(0.75,0.85) 23(1.25,0.85) 24(1.75,0.85) 25(2.25,0.85) 26(2.75,0.85) 27(3.25,0.85) 28(3.75,0.85) 29(4.25,0.85) 30(4.75,0.85) 31(5.25,0.85) 32(5.75,0.85) 33(6.25,0.85) 34(6.75,0.85) 35(7.25,0.85) 36(7.75,0.85) 37(8.25,0.85) 38(8.75,0.85) 39(9.25,0.85) 40(9.75,0.85)
  rect 2.3x3.1 smd mask+0.076: 41(-11.42,-0.85) 42(11.42,-0.85)
  silkscreen extent -12.9,-5.2 12.9,-2.6, body extent -12.72,-3.96 12.71,1.15, height 2.05
6_DFN_3MMX3MM [mm] "Creator MM"
  rect 0.85x0.45 smd mask+0.045: 1(-1.45,1) 2(-1.45,0) 3(-1.45,-1) 4(1.45,-1) 5(1.45,0) 6(1.45,1)
  rect 1.6x2.5 smd mask+0.045: 7(0,0)
  silkscreen extent -2.05,-1.6 1.6,1.75, body extent -1.51,-1.5 1.51,1.5, height 1.13
7M [mm] "Creator MM"
  rect 1.4x1.2 smd mask+0.1: 1(-1.1,-0.85) 2(1.1,-0.85) 3(1.1,0.85) 4(-1.1,0.85)
  silkscreen extent -2.35,-1.4 0.1,1.4, body extent -1.65,-1.3 1.65,1.3, height 0.8
8_SOIC_3.9MM [mm]
  rect 1.2x0.58 smd: 1(-2.8,1.905) 2(-2.8,0.635) 3(-2.8,-0.635) 4(-2.8,-1.905) 5(2.8,-1.905) 6(2.8,-0.635) 7(2.8,0.635) 8(2.8,1.905)
  silkscreen extent -1.91,-2.54 1.91,2.54, body extent -3,-2.45 3,2.45, height 1.75
16-TQFN_3mmx3mm_V1.1 [mm] "Shortend length of pads."
  rect 0.78x0.23 smd mask+0.03: 1(-1.41,0.75) 2(-1.41,0.25) 3(-1.41,-0.25) 4(-1.41,-0.75) 9(1.41,-0.75) 10(1.41,-0.25) 11(1.41,0.25) 12(1.41,0.75)
  rect 0.23x0.78 smd mask+0.03: 5(-0.75,-1.41) 6(-0.25,-1.41) 7(0.25,-1.41) 8(0.75,-1.41) 13(0.75,1.41) 14(0.25,1.41) 15(-0.25,1.41) 16(-0.75,1.41)
  rect 1.6x1.6 smd mask+0.03: 17(0,0)
  silkscreen extent -1.6,-1.6 1.6,1.6, body extent -1.5,-1.5 1.5,1.5, height 0.9
"56-VFQFN EP" [mm] "Creator MM"
  rect 0.8x0.3 smd mask+0.03: 1(-3.95,3.25) 2(-3.95,2.75) 3(-3.95,2.25) 4(-3.95,1.75) 5(-3.95,1.25) 6(-3.95,0.75) 7(-3.95,0.25) 8(-3.95,-0.25) 9(-3.95,-0.75) 10(-3.95,-1.25) 11(-3.95,-1.75) 12(-3.95,-2.25) 13(-3.95,-2.75) 14(-3.95,-3.25) 29(3.95,-3.25) 30(3.95,-2.75) 31(3.95,-2.25) 32(3.95,-1.75) 33(3.95,-1.25) 34(3.95,-0.75) 35(3.95,-0.25) 36(3.95,0.25) 37(3.95,0.75) 38(3.95,1.25) 39(3.95,1.75) 40(3.95,2.25) 41(3.95,2.75) 42(3.95,3.25)
  rect 0.3x0.8 smd mask+0.03: 15(-3.25,-3.95) 16(-2.75,-3.95) 17(-2.25,-3.95) 18(-1.75,-3.95) 19(-1.25,-3.95) 20(-0.75,-3.95) 21(-0.25,-3.95) 22(0.25,-3.95) 23(0.75,-3.95) 24(1.25,-3.95) 25(1.75,-3.95) 26(2.25,-3.95) 27(2.75,-3.95) 28(3.25,-3.95) 43(3.25,3.95) 44(2.75,3.95) 45(2.25,3.95) 46(1.75,3.95) 47(1.25,3.95) 48(0.75,3.95) 49(0.25,3.95) 50(-0.25,3.95) 51(-0.75,3.95) 52(-1.25,3.95) 53(-1.75,3.95) 54(-2.25,3.95) 55(-2.75,3.95) 56(-3.25,3.95)
  rect 4.5x4.3 smd paste-10 mask+0.03: 57(0,0)
  silkscreen extent -4.1,-4.1 4.1,4.1, body extent -4,-4 4,4, height 0.9
96_FPGA_DD3_14MMX10MM-SMALL_SIZE [mm] "Creator MM"
  round 0.35 smd mask+0.05: A1(-3.2,6) A2(-2.4,6) A3(-1.6,6) A7(1.6,6) A8(2.4,6) A9(3.2,6) B1(-3.2,5.2) B2(-2.4,5.2) B3(-1.6,5.2) B7(1.6,5.2) B8(2.4,5.2) B9(3.2,5.2) C1(-3.2,4.4) C2(-2.4,4.4) C3(-1.6,4.4) C7(1.6,4.4) C8(2.4,4.4) C9(3.2,4.4) D1(-3.2,3.6) D2(-2.4,3.6) D3(-1.6,3.6) D7(1.6,3.6) D8(2.4,3.6) D9(3.2,3.6) E1(-3.2,2.8) E2(-2.4,2.8) E3(-1.6,2.8) E7(1.6,2.8) E8(2.4,2.8) E9(3.2,2.8) F1(-3.2,2) F2(-2.4,2) F3(-1.6,2) F7(1.6,2) F8(2.4,2) F9(3.2,2) G1(-3.2,1.2) G2(-2.4,1.2) G3(-1.6,1.2) G7(1.6,1.2) G8(2.4,1.2) G9(3.2,1.2) H1(-3.2,0.4) H2(-2.4,0.4) H3(-1.6,0.4) H7(1.6,0.4) H8(2.4,0.4) H9(3.2,0.4) J1(-3.2,-0.4) J2(-2.4,-0.4) J3(-1.6,-0.4) J7(1.6,-0.4) J8(2.4,-0.4) J9(3.2,-0.4) K1(-3.2,-1.2) K2(-2.4,-1.2) K3(-1.6,-1.2) K7(1.6,-1.2) K8(2.4,-1.2) K9(3.2,-1.2) L1(-3.2,-2) L2(-2.4,-2) L3(-1.6,-2) L7(1.6,-2) L8(2.4,-2) L9(3.2,-2) M1(-3.2,-2.8) M2(-2.4,-2.8) M3(-1.6,-2.8) M7(1.6,-2.8) M8(2.4,-2.8) M9(3.2,-2.8) N1(-3.2,-3.6) N2(-2.4,-3.6) N3(-1.6,-3.6) N7(1.6,-3.6) N8(2.4,-3.6) N9(3.2,-3.6) P1(-3.2,-4.4) P2(-2.4,-4.4) P3(-1.6,-4.4) P7(1.6,-4.4) P8(2.4,-4.4) P9(3.2,-4.4) R1(-3.2,-5.2) R2(-2.4,-5.2) R3(-1.6,-5.2) R7(1.6,-5.2) R8(2.4,-5.2) R9(3.2,-5.2) T1(-3.2,-6) T2(-2.4,-6) T3(-1.6,-6) T7(1.6,-6) T8(2.4,-6) T9(3.2,-6)
  silkscreen extent -5.1,-7.1 5.1,7.1, body extent -5,-7 5,7, height 1.2
0532610471 [mm] "Creator MM"
  rect 1.6x0.8 smd mask+0.06: 1(-1.45,-1.875) 2(-1.45,-0.625) 3(-1.45,0.625) 4(-1.45,1.875)
  rect 3x2.1 smd mask+0.06: 5(1.45,-4.425) 6(1.45,4.425)
  silkscreen extent -1.4,-3.5 3.7,3.5, body extent -1.6,-5.08 3.6,5.07, height 3.39
693071010811 [mm]
  rect 0.8x1.5 smd mask+0.09: 1(-1.815,3.225) 2(-0.715,2.825) 3(0.385,3.225) 4(1.485,3.425) 5(2.585,3.225) 6(3.685,3.425) 7(4.785,3.225) 8(5.885,3.225)
  rect 1.8x1.4 smd: 9(-0.625,-7.075) 10(5.075,-7.075)
  rect 1.5x1.9 smd: 11(6.775,6.075)
  rect 1.6x1.9 smd: 12(-6.675,7.075)
  silkscreen extent -7.07,-7.57 7.22,9.6, body extent -6.87,-7.46 7.13,7.75, height 1.83
ABM8 [mm] "Creator MM"
  rect 1.35x1.15 smd mask+0.1: 1(-1.125,-0.875) 2(1.125,-0.875) 3(1.125,0.875) 4(-1.125,0.875)
  silkscreen extent -2.35,-1.4 0.1,1.4, body extent -1.6,-1.25 1.6,1.25, height 0.76
ABM8G [mm] "Creator MM"
  rect 1.4x1.2 smd mask+0.1: 1(-1.1,-0.85) 2(1.1,-0.85) 3(1.1,0.85) 4(-1.1,0.85)
  silkscreen extent -1.9,-1.9 0.1,1.4, body extent -1.6,-1.25 1.6,1.25, height 1.02
ABS06 [mm]
  rect 0.75x1.4 smd: 1(-0.725,0) 2(0.725,0)
  silkscreen extent -1.4,-1 1.4,1, body extent -1,-0.62 1,0.6, height 0.61
ACM2012 [mm]
  rect 0.75x0.4 smd mask+0.076: 1(-0.925,0.4) 2(-0.925,-0.4) 3(0.925,-0.4) 4(0.925,0.4)
  silkscreen extent -1.1,-0.9 1.1,0.9, body extent -1.2,-0.7 1.2,0.7, height 1.3
C0201 [mm] "Creator MM"
  rect 0.3x0.3 smd mask+0.04: 1(-0.265,0) 2(0.265,0)
  silkscreen extent -0.6,-0.3 0.6,0.3, body extent -0.3,-0.15 0.3,0.15, height 0.3
C0402 [mm]
  rect 0.5x0.5 smd: 1(-0.5,0) 2(0.5,0)
  silkscreen extent -1,-0.5 1,0.5, body extent -0.5,-0.25 0.5,0.25, height 0.56
C0603 [mm]
  rect 0.8x0.8 smd: 1(-0.75,0) 2(0.75,0)
  silkscreen extent -1.4,-0.7 1.4,0.7, body extent -0.8,-0.42 0.8,0.44, height 0.95
C0603_small [mm] "Creator MM"
  rect 0.7x0.8 smd: 1(-0.65,0) 2(0.65,0)
  silkscreen extent -1.3,-0.7 1.3,0.7, body extent -0.8,-0.42 0.8,0.44, height 0.95
C0805 [mm]
  rect 0.9x1.3 smd: 1(-0.95,0) 2(0.95,0)
  silkscreen extent -1.78,-1.02 1.78,1.02, body extent -1,-0.6 1,0.6, height 1.5
"C1206 -  TLN S CASE TANTAL" [mm] "Creator MM"
  rect 1.15x1.2 smd: 1(-1.175,0) 2(1.175,0)
  silkscreen extent -2.29,-1.14 2.29,1.14, body extent -1.6,-0.8 1.6,0.8, height 1.21
C2312 [mm] "Creator MM. Footprint density lvl B"
  rect 2.1x2.5 smd mask+0.09: 1(-2.45,0) 2(2.45,0)
  silkscreen extent -4.07,-1.7 3.8,1.7, body extent -3.09,-1.61 3.09,1.6, height 2.7
C2917 [mm] "Creator MM. Footprint density lvl B"
  rect 2.37x2.43 smd: 1(-3.12,0) 2(3.12,0)
  silkscreen extent -4.64,-2.65 4.65,2.65, body extent -3.79,-2.3 3.81,2.3, height 3.1
DBV_SOT_23_6 [mm]
  rect 1x0.55 smd: 1(-1.35,0.95) 2(-1.35,0) 3(-1.35,-0.95) 4(1.35,-0.95) 5(1.35,0) 6(1.35,0.95)
  silkscreen extent -2,-1.59 0.9,1.74, body extent -1.59,-1.59 1.59,1.59, height 1.45
ESQ-120-14-G-D [mm] "Creator MM"
  rect 2x1.6 hole 1.1: 1(0,0)
  oval 2x1.6 hole 1.1: 2(-2.54,0) 3(0,-2.54) 4(-2.54,-2.54) 5(0,-5.08) 6(-2.54,-5.08) 7(0,-7.62) 8(-2.54,-7.62) 9(0,-10.16) 10(-2.54,-10.16) 11(0,-12.7) 12(-2.54,-12.7) 13(0,-15.24) 14(-2.54,-15.24) 15(0,-17.78) 16(-2.54,-17.78) 17(0,-20.32) 18(-2.54,-20.32) 19(0,-22.86) 20(-2.54,-22.86) 21(0,-25.4) 22(-2.54,-25.4) 23(0,-27.94) 24(-2.54,-27.94) 25(0,-30.48) 26(-2.54,-30.48) 27(0,-33.02) 28(-2.54,-33.02) 29(0,-35.56) 30(-2.54,-35.56) 31(0,-38.1) 32(-2.54,-38.1) 33(0,-40.64) 34(-2.54,-40.64) 35(0,-43.18) 36(-2.54,-43.18) 37(0,-45.72) 38(-2.54,-45.72) 39(0,-48.26) 40(-2.54,-48.26)
  silkscreen extent -3.84,-49.93 1.3,1.67, body extent -3.81,-49.78 1.27,1.52, height 12.11
ESQ-120-14-G-S [mm] "Creator MM"
  rect 2x1.6 hole 1.1: 1(0,0)
  oval 2x1.6 hole 1.1: 2(0,-2.54) 3(0,-5.08) 4(0,-7.62) 5(0,-10.16) 6(0,-12.7) 7(0,-15.24) 8(0,-17.78) 9(0,-20.32) 10(0,-22.86) 11(0,-25.4) 12(0,-27.94) 13(0,-30.48) 14(0,-33.02) 15(0,-35.56) 16(0,-38.1) 17(0,-40.64) 18(0,-43.18) 19(0,-45.72) 20(0,-48.26)
  silkscreen extent -1.3,-49.93 1.3,1.67, body extent -1.27,-49.78 1.27,1.52, height 11.11
FC68125 [mm]
  oval 2.4x2.7 hole 1.4: 1(0,0)
  oval 2.7x2.4 hole 1.4: 2(-0.9,-2.85) 3(-9,3.4) 4(-9,-3.4) 6(-0.9,2.85)
  round 1.1 hole 1.1 unplated: 5(-10.4,0) 7(-3.4,0)
  silkscreen extent -15,-3.7 0.3,3.7, body extent -14.88,-3.6 0.2,3.6, height 6
FID_40X52D#1 [mm]
  round 1.016 smd paste-1.016 mask+0.15: 1(-0.3,0.3)
FID_40X52D#2 [mm]
  round 1.016 smd paste-1.016 mask+0.15: 1(0,0)
FID_40X52D#3 [mm]
  round 1.016 smd paste-1.016 mask+0.15: 1(0,0.5)
"HDMI V1.1" [mm] "Changed holes to slots"
  rect 2.6x0.3 smd mask+0.025: 1(-3.36,4.5) 2(-3.36,4) 3(-3.36,3.5) 4(-3.36,3) 5(-3.36,2.5) 6(-3.36,2) 7(-3.36,1.5) 8(-3.36,1) 9(-3.36,0.5) 10(-3.36,0) 11(-3.36,-0.5) 12(-3.36,-1) 13(-3.36,-1.5) 14(-3.36,-2) 15(-3.36,-2.5) 16(-3.36,-3) 17(-3.36,-3.5) 18(-3.36,-4) 19(-3.36,-4.5)
  oval 3.7x1.7 hole 0.9 slot 2.7 at 0 deg: MTG1(-2.6,7.25) MTG3(-2.6,-7.25)
  oval 2.7x1.7 hole 0.9 slot 1.7 at 0 deg: MTG2(3.36,7.25) MTG4(3.36,-7.25)
  silkscreen extent -5.1,-10 12.05,10, body extent -4.2,-7.5 7.95,7.5, height 6.28
HDR_1X2_2.54MM [mm]
  rect 2x1.6 hole 1.1: 1(0,0)
  oval 2x1.6 hole 1.1: 2(0,-2.54)
  silkscreen extent -1.3,-3.81 1.3,1.27, body extent -1.2,-3.62 1.2,1.06, height 8.4
HDR_1X6_2.54MM [mm] "Creator MM"
  rect 2x1.6 hole 1.1: 1(0,0)
  oval 2x1.6 hole 1.1: 2(0,-2.54) 3(0,-5.08) 4(0,-7.62) 5(0,-10.16) 6(0,-12.7)
  silkscreen extent -1.3,-13.97 1.3,1.27, body extent -1.2,-13.77 1.2,1.07, height 8.4
HVQFN33_7X7MM [mm] "Creator MM"
  rect 1.1x0.3 smd mask+0.06: 1(-3.35,2.275) 2(-3.35,1.625) 3(-3.35,0.975) 4(-3.35,0.325) 5(-3.35,-0.325) 6(-3.35,-0.975) 7(-3.35,-1.625) 8(-3.35,-2.275) 17(3.35,-2.275) 18(3.35,-1.625) 19(3.35,-0.975) 20(3.35,-0.325) 21(3.35,0.325) 22(3.35,0.975) 23(3.35,1.625) 24(3.35,2.275)
  rect 0.3x1.1 smd mask+0.06: 9(-2.275,-3.35) 10(-1.625,-3.35) 11(-0.975,-3.35) 12(-0.325,-3.35) 13(0.325,-3.35) 14(0.975,-3.35) 15(1.625,-3.35) 16(2.275,-3.35) 25(2.275,3.35) 26(1.625,3.35) 27(0.975,3.35) 28(0.325,3.35) 29(-0.325,3.35) 30(-0.975,3.35) 31(-1.625,3.35) 32(-2.275,3.35)
  rect 4.85x4.85 smd paste-10 mask+0.06: 33(0,0)
  silkscreen extent -3.6,-3.6 3.6,3.6, body extent -3.5,-3.5 3.5,3.5, height 1
IFSC_79MILX98MIL [mm] "Creator MM"
  rect 1.3x2.1 smd: 1(-1.05,0) 2(1.05,0)
  silkscreen extent -0.1,-1.1 0.1,1.1, body extent -1.3,-1 1.3,1, height 1.2
IHLP_118MILX144MIL [mm] "Creator MM"
  rect 1.5x1.2 smd: 1(-1.35,0) 2(1.35,0)
  silkscreen extent -1.9,-1.6 1.9,1.6, body extent -1.9,-1.5 1.9,1.5, height 1.5
IHLP_160MILX175MIL [mm] "Creator MM"
  rect 1.9x2.3 smd: 1(-1.9,0) 2(1.9,0)
  silkscreen extent -2.3,-2.2 2.3,2.2, body extent -2.3,-2.1 2.3,2.1, height 1.2
IHLP_204MILX216MIL [mm] "Creator MM"
  rect 2.115x2.79 smd: 1(-2.137,0) 2(2.138,0)
  silkscreen extent -2.9,-2.7 2.9,2.7, body extent -2.75,-2.6 2.75,2.6, height 3
L829-1J1T-43 [mil]
  round 60 hole 35.43: 1(-200,-305) 2(-120,-305) 3(-40,-305) 4(40,-305) 5(120,-305) 6(200,-305) 7(-240,-405) 8(-160,-405) 9(-80,-405) 10(80,-405) 11(160,-405) 12(240,-405)
  round 75 hole 51.18: 13(-296,205) 14(-296,305) 15(296,105) 16(296,205) 17(296,305)
  round 100 hole 63: 18(-346,-45) 19(346,-45)
  round 0 hole 129.92: ""(-190,-45) ""(190,-45)
  silkscreen extent -346,-475 346,475, body extent -401,-472 401,494, height 494
LED_0603 [mm]
  rect 0.8x0.8 smd: 1(-0.8,0) 2(0.8,0)
  silkscreen extent -1.78,-0.76 1.52,0.76, body extent -0.85,-0.4 0.85,0.4, height 0.66
MH_5MMD_2MMD [mm]
  round 5 / inner round 3.683 / far side round 5 hole 2: 1(0,0)
MH_7.4MMD_3.2MMD [mm]
  round 7.4 / inner round 3.683 / far side round 7.4 hole 3.2 mask+0.025: 1(0,0)
MICRO_SD_CARD [mm] ".Creator MM"
  body extent -8.65,-13.74 2.35,1.26, height 1.95
MICRO_SIM_CARD [mm] "Creator MM"
  body extent 0,-15 12,0, height 1.7
MINI_PCIE_52PIN_CARD_CON [mm] "Creator MM"
  rect 2x0.6 smd mask+0.05: 1(-4.1,-0.7) 2(4.1,-1.1) 3(-4.1,-1.5) 4(4.1,-1.9) 5(-4.1,-2.3) 6(4.1,-2.7) 7(-4.1,-3.1) 8(4.1,-3.5) 9(-4.1,-3.9) 10(4.1,-4.3) 11(-4.1,-4.7) 12(4.1,-5.1) 13(-4.1,-5.5) 14(4.1,-5.9) 15(-4.1,-6.3) 16(4.1,-6.7) 17(-4.1,-10.3) 18(4.1,-10.7) 19(-4.1,-11.1) 20(4.1,-11.5) 21(-4.1,-11.9) 22(4.1,-12.3) 23(-4.1,-12.7) 24(4.1,-13.1) 25(-4.1,-13.5) 26(4.1,-13.9) 27(-4.1,-14.3) 28(4.1,-14.7) 29(-4.1,-15.1) 30(4.1,-15.5) 31(-4.1,-15.9) 32(4.1,-16.3) 33(-4.1,-16.7) 34(4.1,-17.1) 35(-4.1,-17.5) 36(4.1,-17.9) 37(-4.1,-18.3) 38(4.1,-18.7) 39(-4.1,-19.1) 40(4.1,-19.5) 41(-4.1,-19.9) 42(4.1,-20.3) 43(-4.1,-20.7) 44(4.1,-21.1) 45(-4.1,-21.5) 46(4.1,-21.9) 47(-4.1,-22.3) 48(4.1,-22.7) 49(-4.1,-23.1) 50(4.1,-23.5) 51(-4.1,-23.9) 52(4.1,-24.3)
  rect 3.2x2.3 smd: 53(-3.5,2.15) 54(-3.5,-27.15)
  rrect70% 0x0 hole 1.6 unplated: 55(0,0)
  rrect70% 0x0 hole 1.1 unplated: 56(0,-25)
  silkscreen extent -5.1,-26.8 5.1,1.8, body extent -5,-27.35 5,2.35, height 5.95
MINI_PCIE_52PIN_CARD_LATCH [mm] "Creator MM"
  rect 2.7x1.2 smd mask+0.09: 1(-3.15,1.25) 2(-3.15,-1.25) 4(-3.15,-22.95) 5(-3.15,-25.45)
  rect 1.9x1.5 smd mask+0.09: 3(2.75,0) 6(2.75,-24.2)
  rrect70% 0x0 hole 1.55 mask+0.09: 7(0,0)
  rrect70% 0x0 hole 1.05 mask+0.09: 8(0,-24.2)
  silkscreen extent -3.35,-26.6 3.95,2.4, body extent -3.95,-26.6 3.95,2.4, height 6.7
"MINI_PCIE_FULL CARD" [mm] ".Creator MM"
  body extent 0,0 50.95,30, height 6.9
MLF_3X3_12PINS [mm]
  rect 0.48x0.23 smd mask+0.076: 1(-1.36,1.25) 2(-1.36,0.75) 3(-1.36,0.25) 4(-1.36,-0.25) 5(-1.36,-0.75) 6(-1.36,-1.25) 7(1.36,-1.25) 8(1.36,-0.75) 9(1.36,-0.25) 10(1.36,0.25) 11(1.36,0.75) 12(1.36,1.25)
  rect 1.8x1.125 smd mask+0.025: 13(0,0.699)
  rect 0.4x1.19 smd mask+0.076: 14(-0.77,-0.73)
  rect 0.9x1.19 smd mask+0.025: 15(0.45,-0.73)
  silkscreen extent -1.52,-1.65 1.52,2.1, body extent -1.52,-1.65 1.52,1.65, height 0.9
"MSOP8 _SMALLER" [mm]
  rect 1.04x0.38 smd mask+0.076: 1(-1.9,0.975) 2(-1.9,0.325) 3(-1.9,-0.325) 4(-1.9,-0.975) 5(1.9,-0.975) 6(1.9,-0.325) 7(1.9,0.325) 8(1.9,0.975)
  silkscreen extent -1.5,-1.6 1.5,1.6, body extent -1.5,-1.6 1.5,1.6, height 0.9
PBGA624 [mm] "Creator MM"
  round 0.4 smd mask+0.05: A2(-8.8,9.6) A3(-8,9.6) A4(-7.2,9.6) A5(-6.4,9.6) A6(-5.6,9.6) A7(-4.8,9.6) A8(-4,9.6) A9(-3.2,9.6) A10(-2.4,9.6) A11(-1.6,9.6) A12(-0.8,9.6) A13(0,9.6) A14(0.8,9.6) A15(1.6,9.6) A16(2.4,9.6) A17(3.2,9.6) A18(4,9.6) A19(4.8,9.6) A20(5.6,9.6) A21(6.4,9.6) A22(7.2,9.6) A23(8,9.6) A24(8.8,9.6) A25(9.6,9.6) AA1(-9.6,-6.4) AA2(-8.8,-6.4) AA3(-8,-6.4) AA4(-7.2,-6.4) AA5(-6.4,-6.4) AA6(-5.6,-6.4) AA7(-4.8,-6.4) AA8(-4,-6.4) AA9(-3.2,-6.4) AA10(-2.4,-6.4) AA11(-1.6,-6.4) AA12(-0.8,-6.4) AA13(0,-6.4) AA14(0.8,-6.4) AA15(1.6,-6.4) AA16(2.4,-6.4) AA17(3.2,-6.4) AA18(4,-6.4) AA19(4.8,-6.4) AA20(5.6,-6.4) AA21(6.4,-6.4) AA22(7.2,-6.4) AA23(8,-6.4) AA24(8.8,-6.4) AA25(9.6,-6.4) AB1(-9.6,-7.2) AB2(-8.8,-7.2) AB3(-8,-7.2) AB4(-7.2,-7.2) AB5(-6.4,-7.2) AB6(-5.6,-7.2) AB7(-4.8,-7.2) AB8(-4,-7.2) AB9(-3.2,-7.2) AB10(-2.4,-7.2) AB11(-1.6,-7.2) AB12(-0.8,-7.2) AB13(0,-7.2) AB14(0.8,-7.2) AB15(1.6,-7.2) AB16(2.4,-7.2) AB17(3.2,-7.2) AB18(4,-7.2) AB19(4.8,-7.2) AB20(5.6,-7.2) AB21(6.4,-7.2) AB22(7.2,-7.2) AB23(8,-7.2) AB24(8.8,-7.2) AB25(9.6,-7.2) AC1(-9.6,-8) AC2(-8.8,-8) AC3(-8,-8) AC4(-7.2,-8) AC5(-6.4,-8) AC6(-5.6,-8) AC7(-4.8,-8) AC8(-4,-8) AC9(-3.2,-8) AC10(-2.4,-8) AC11(-1.6,-8) AC12(-0.8,-8) AC13(0,-8) AC14(0.8,-8) AC15(1.6,-8) AC16(2.4,-8) AC17(3.2,-8) AC18(4,-8) AC19(4.8,-8) AC20(5.6,-8) AC21(6.4,-8) AC22(7.2,-8) AC23(8,-8) AC24(8.8,-8) AC25(9.6,-8) AD1(-9.6,-8.8) AD2(-8.8,-8.8) AD3(-8,-8.8) AD4(-7.2,-8.8) AD5(-6.4,-8.8) AD6(-5.6,-8.8) AD7(-4.8,-8.8) AD8(-4,-8.8) AD9(-3.2,-8.8) AD10(-2.4,-8.8) AD11(-1.6,-8.8) AD12(-0.8,-8.8) AD13(0,-8.8) AD14(0.8,-8.8) AD15(1.6,-8.8) AD16(2.4,-8.8) AD17(3.2,-8.8) AD18(4,-8.8) AD19(4.8,-8.8) AD20(5.6,-8.8) AD21(6.4,-8.8) AD22(7.2,-8.8) AD23(8,-8.8) AD24(8.8,-8.8) AD25(9.6,-8.8) AE1(-9.6,-9.6) AE2(-8.8,-9.6) AE3(-8,-9.6) AE4(-7.2,-9.6) AE5(-6.4,-9.6) AE6(-5.6,-9.6) AE7(-4.8,-9.6) AE8(-4,-9.6) AE9(-3.2,-9.6) AE10(-2.4,-9.6) AE11(-1.6,-9.6) AE12(-0.8,-9.6) AE13(0,-9.6) AE14(0.8,-9.6) AE15(1.6,-9.6) AE16(2.4,-9.6) AE17(3.2,-9.6) AE18(4,-9.6) AE19(4.8,-9.6) AE20(5.6,-9.6) AE21(6.4,-9.6) AE22(7.2,-9.6) AE23(8,-9.6) AE24(8.8,-9.6) AE25(9.6,-9.6) B1(-9.6,8.8) B2(-8.8,8.8) B3(-8,8.8) B4(-7.2,8.8) B5(-6.4,8.8) B6(-5.6,8.8) B7(-4.8,8.8) B8(-4,8.8) B9(-3.2,8.8) B10(-2.4,8.8) B11(-1.6,8.8) B12(-0.8,8.8) B13(0,8.8) B14(0.8,8.8) B15(1.6,8.8) B16(2.4,8.8) B17(3.2,8.8) B18(4,8.8) B19(4.8,8.8) B20(5.6,8.8) B21(6.4,8.8) B22(7.2,8.8) B23(8,8.8) B24(8.8,8.8) B25(9.6,8.8) C1(-9.6,8) C2(-8.8,8) C3(-8,8) C4(-7.2,8) C5(-6.4,8) C6(-5.6,8) C7(-4.8,8) C8(-4,8) C9(-3.2,8) C10(-2.4,8) C11(-1.6,8) C12(-0.8,8) C13(0,8) C14(0.8,8) C15(1.6,8) C16(2.4,8) C17(3.2,8) C18(4,8) C19(4.8,8) C20(5.6,8) C21(6.4,8) C22(7.2,8) C23(8,8) C24(8.8,8) C25(9.6,8) D1(-9.6,7.2) D2(-8.8,7.2) D3(-8,7.2) D4(-7.2,7.2) D5(-6.4,7.2) D6(-5.6,7.2) D7(-4.8,7.2) D8(-4,7.2) D9(-3.2,7.2) D10(-2.4,7.2) D11(-1.6,7.2) D12(-0.8,7.2) D13(0,7.2) D14(0.8,7.2) D15(1.6,7.2) D16(2.4,7.2) D17(3.2,7.2) D18(4,7.2) D19(4.8,7.2) D20(5.6,7.2) D21(6.4,7.2) D22(7.2,7.2) D23(8,7.2) D24(8.8,7.2) D25(9.6,7.2) E1(-9.6,6.4) E2(-8.8,6.4) E3(-8,6.4) E4(-7.2,6.4) E5(-6.4,6.4) E6(-5.6,6.4) E7(-4.8,6.4) E8(-4,6.4) E9(-3.2,6.4) E10(-2.4,6.4) E11(-1.6,6.4) E12(-0.8,6.4) E13(0,6.4) E14(0.8,6.4) E15(1.6,6.4) E16(2.4,6.4) E17(3.2,6.4) E18(4,6.4) E19(4.8,6.4) E20(5.6,6.4) E21(6.4,6.4) E22(7.2,6.4) E23(8,6.4) E24(8.8,6.4) E25(9.6,6.4) F1(-9.6,5.6) F2(-8.8,5.6) F3(-8,5.6) F4(-7.2,5.6) F5(-6.4,5.6) F6(-5.6,5.6) F7(-4.8,5.6) F8(-4,5.6) F9(-3.2,5.6) F10(-2.4,5.6) F11(-1.6,5.6) F12(-0.8,5.6) F13(0,5.6) F14(0.8,5.6) F15(1.6,5.6) F16(2.4,5.6) F17(3.2,5.6) F18(4,5.6) F19(4.8,5.6) F20(5.6,5.6) F21(6.4,5.6) F22(7.2,5.6) F23(8,5.6) F24(8.8,5.6) F25(9.6,5.6) G1(-9.6,4.8) G2(-8.8,4.8) G3(-8,4.8) G4(-7.2,4.8) G5(-6.4,4.8) G6(-5.6,4.8) G7(-4.8,4.8) G8(-4,4.8) G9(-3.2,4.8) G10(-2.4,4.8) G11(-1.6,4.8) G12(-0.8,4.8) G13(0,4.8) G14(0.8,4.8) G15(1.6,4.8) G16(2.4,4.8) G17(3.2,4.8) G18(4,4.8) G19(4.8,4.8) G20(5.6,4.8) G21(6.4,4.8) G22(7.2,4.8) G23(8,4.8) G24(8.8,4.8) G25(9.6,4.8) H1(-9.6,4) H2(-8.8,4) H3(-8,4) H4(-7.2,4) H5(-6.4,4) H6(-5.6,4) H7(-4.8,4) H8(-4,4) H9(-3.2,4) H10(-2.4,4) H11(-1.6,4) H12(-0.8,4) H13(0,4) H14(0.8,4) H15(1.6,4) H16(2.4,4) H17(3.2,4) H18(4,4) H19(4.8,4) H20(5.6,4) H21(6.4,4) H22(7.2,4) H23(8,4) H24(8.8,4) H25(9.6,4) J1(-9.6,3.2) J2(-8.8,3.2) J3(-8,3.2) J4(-7.2,3.2) J5(-6.4,3.2) J6(-5.6,3.2) J7(-4.8,3.2) J8(-4,3.2) J9(-3.2,3.2) J10(-2.4,3.2) J11(-1.6,3.2) J12(-0.8,3.2) J13(0,3.2) J14(0.8,3.2) J15(1.6,3.2) J16(2.4,3.2) J17(3.2,3.2) J18(4,3.2) J19(4.8,3.2) J20(5.6,3.2) J21(6.4,3.2) J22(7.2,3.2) J23(8,3.2) J24(8.8,3.2) J25(9.6,3.2) K1(-9.6,2.4) K2(-8.8,2.4) K3(-8,2.4) K4(-7.2,2.4) K5(-6.4,2.4) K6(-5.6,2.4) K7(-4.8,2.4) K8(-4,2.4) K9(-3.2,2.4) K10(-2.4,2.4) K11(-1.6,2.4) K12(-0.8,2.4) K13(0,2.4) K14(0.8,2.4) K15(1.6,2.4) K16(2.4,2.4) K17(3.2,2.4) K18(4,2.4) K19(4.8,2.4) K20(5.6,2.4) K21(6.4,2.4) K22(7.2,2.4) K23(8,2.4) K24(8.8,2.4) K25(9.6,2.4) L1(-9.6,1.6) L2(-8.8,1.6) L3(-8,1.6) L4(-7.2,1.6) L5(-6.4,1.6) L6(-5.6,1.6) L7(-4.8,1.6) L8(-4,1.6) L9(-3.2,1.6) L10(-2.4,1.6) L11(-1.6,1.6) L12(-0.8,1.6) L13(0,1.6) L14(0.8,1.6) L15(1.6,1.6) L16(2.4,1.6) L17(3.2,1.6) L18(4,1.6) L19(4.8,1.6) L20(5.6,1.6) L21(6.4,1.6) L22(7.2,1.6) L23(8,1.6) L24(8.8,1.6) L25(9.6,1.6) M1(-9.6,0.8) M2(-8.8,0.8) M3(-8,0.8) M4(-7.2,0.8) M5(-6.4,0.8) M6(-5.6,0.8) M7(-4.8,0.8) M8(-4,0.8) M9(-3.2,0.8) M10(-2.4,0.8) M11(-1.6,0.8) M12(-0.8,0.8) M13(0,0.8) M14(0.8,0.8) M15(1.6,0.8) M16(2.4,0.8) M17(3.2,0.8) M18(4,0.8) M19(4.8,0.8) M20(5.6,0.8) M21(6.4,0.8) M22(7.2,0.8) M23(8,0.8) M24(8.8,0.8) M25(9.6,0.8) N1(-9.6,0) N2(-8.8,0) N3(-8,0) N4(-7.2,0) N5(-6.4,0) N6(-5.6,0) N7(-4.8,0) N8(-4,0) N9(-3.2,0) N10(-2.4,0) N11(-1.6,0) N12(-0.8,0) N13(0,0) N14(0.8,0) N15(1.6,0) N16(2.4,0) N17(3.2,0) N18(4,0) N19(4.8,0) N20(5.6,0) N21(6.4,0) N22(7.2,0) N23(8,0) N24(8.8,0) N25(9.6,0) P1(-9.6,-0.8) P2(-8.8,-0.8) P3(-8,-0.8) P4(-7.2,-0.8) P5(-6.4,-0.8) P6(-5.6,-0.8) P7(-4.8,-0.8) P8(-4,-0.8) P9(-3.2,-0.8) P10(-2.4,-0.8) P11(-1.6,-0.8) P12(-0.8,-0.8) P13(0,-0.8) P14(0.8,-0.8) P15(1.6,-0.8) P16(2.4,-0.8) P17(3.2,-0.8) P18(4,-0.8) P19(4.8,-0.8) P20(5.6,-0.8) P21(6.4,-0.8) P22(7.2,-0.8) P23(8,-0.8) P24(8.8,-0.8) P25(9.6,-0.8) R1(-9.6,-1.6) R2(-8.8,-1.6) R3(-8,-1.6) R4(-7.2,-1.6) R5(-6.4,-1.6) R6(-5.6,-1.6) R7(-4.8,-1.6) R8(-4,-1.6) R9(-3.2,-1.6) R10(-2.4,-1.6) R11(-1.6,-1.6) R12(-0.8,-1.6) R13(0,-1.6) R14(0.8,-1.6) R15(1.6,-1.6) R16(2.4,-1.6) R17(3.2,-1.6) R18(4,-1.6) R19(4.8,-1.6) R20(5.6,-1.6) R21(6.4,-1.6) R22(7.2,-1.6) R23(8,-1.6) R24(8.8,-1.6) R25(9.6,-1.6) T1(-9.6,-2.4) T2(-8.8,-2.4) T3(-8,-2.4) T4(-7.2,-2.4) T5(-6.4,-2.4) T6(-5.6,-2.4) T7(-4.8,-2.4) T8(-4,-2.4) T9(-3.2,-2.4) T10(-2.4,-2.4) T11(-1.6,-2.4) T12(-0.8,-2.4) T13(0,-2.4) T14(0.8,-2.4) T15(1.6,-2.4) T16(2.4,-2.4) T17(3.2,-2.4) T18(4,-2.4) T19(4.8,-2.4) T20(5.6,-2.4) T21(6.4,-2.4) T22(7.2,-2.4) T23(8,-2.4) T24(8.8,-2.4) T25(9.6,-2.4) U1(-9.6,-3.2) U2(-8.8,-3.2) U3(-8,-3.2) U4(-7.2,-3.2) U5(-6.4,-3.2) U6(-5.6,-3.2) U7(-4.8,-3.2) U8(-4,-3.2) U9(-3.2,-3.2) U10(-2.4,-3.2) U11(-1.6,-3.2) U12(-0.8,-3.2) U13(0,-3.2) U14(0.8,-3.2) U15(1.6,-3.2) U16(2.4,-3.2) U17(3.2,-3.2) U18(4,-3.2) U19(4.8,-3.2) U20(5.6,-3.2) U21(6.4,-3.2) U22(7.2,-3.2) U23(8,-3.2) U24(8.8,-3.2) U25(9.6,-3.2) V1(-9.6,-4) V2(-8.8,-4) V3(-8,-4) V4(-7.2,-4) V5(-6.4,-4) V6(-5.6,-4) V7(-4.8,-4) V8(-4,-4) V9(-3.2,-4) V10(-2.4,-4) V11(-1.6,-4) V12(-0.8,-4) V13(0,-4) V14(0.8,-4) V15(1.6,-4) V16(2.4,-4) V17(3.2,-4) V18(4,-4) V19(4.8,-4) V20(5.6,-4) V21(6.4,-4) V22(7.2,-4) V23(8,-4) V24(8.8,-4) V25(9.6,-4) W1(-9.6,-4.8) W2(-8.8,-4.8) W3(-8,-4.8) W4(-7.2,-4.8) W5(-6.4,-4.8) W6(-5.6,-4.8) W7(-4.8,-4.8) W8(-4,-4.8) W9(-3.2,-4.8) W10(-2.4,-4.8) W11(-1.6,-4.8) W12(-0.8,-4.8) W13(0,-4.8) W14(0.8,-4.8) W15(1.6,-4.8) W16(2.4,-4.8) W17(3.2,-4.8) W18(4,-4.8) W19(4.8,-4.8) W20(5.6,-4.8) W21(6.4,-4.8) W22(7.2,-4.8) W23(8,-4.8) W24(8.8,-4.8) W25(9.6,-4.8) Y1(-9.6,-5.6) Y2(-8.8,-5.6) Y3(-8,-5.6) Y4(-7.2,-5.6) Y5(-6.4,-5.6) Y6(-5.6,-5.6) Y7(-4.8,-5.6) Y8(-4,-5.6) Y9(-3.2,-5.6) Y10(-2.4,-5.6) Y11(-1.6,-5.6) Y12(-0.8,-5.6) Y13(0,-5.6) Y14(0.8,-5.6) Y15(1.6,-5.6) Y16(2.4,-5.6) Y17(3.2,-5.6) Y18(4,-5.6) Y19(4.8,-5.6) Y20(5.6,-5.6) Y21(6.4,-5.6) Y22(7.2,-5.6) Y23(8,-5.6) Y24(8.8,-5.6) Y25(9.6,-5.6)
  silkscreen extent -10.6,-10.6 10.6,10.6, body extent -10.5,-10.5 10.5,10.5, height 1.1
POWER_JACK_5.5_2.1MM_NS_V1.1 [mm] "Creator MM. v1.1 - changed holes for slots"
  oval 5x4 hole 1 slot 3.7 at 0 deg: 1(0,0)
  oval 5x4 hole 1 slot 3.2 at 0 deg: 2(0,6)
  oval 4x5 hole 1 slot 3.2 at 90 deg: 3(-4.7,3)
  silkscreen extent -4.65,-0.85 4.65,19.85, body extent -4.9,-0.7 4.5,13.7, height 11.02
QFN16_3X3MM [mm] "Creator MM"
  rect 0.8x0.3 smd mask+0.03: 1(-1.275,1) 2(-1.275,0.5) 3(-1.275,0) 4(-1.275,-0.5) 5(-1.275,-1) 9(1.275,-1) 10(1.275,-0.5) 11(1.275,0) 12(1.275,0.5) 13(1.275,1)
  rect 0.3x0.8 smd mask+0.03: 6(-0.5,-1.275) 7(0,-1.275) 8(0.5,-1.275) 14(0.5,1.275) 15(0,1.275) 16(-0.5,1.275)
  silkscreen extent -1.9,-1.6 1.6,1.6, body extent -1.5,-1.5 1.5,1.5, height 1.02
QFN24_4X4MM [mm] "Creator MM"
  rect 1x0.3 smd mask+0.03: 1(-1.875,1.5) 2(-1.875,1) 3(-1.875,0.5) 4(-1.875,0) 5(-1.875,-0.5) 6(-1.875,-1) 7(-1.875,-1.5) 13(1.875,-1.5) 14(1.875,-1) 15(1.875,-0.5) 16(1.875,0) 17(1.875,0.5) 18(1.875,1) 19(1.875,1.5)
  rect 0.3x1 smd mask+0.03: 8(-1,-1.875) 9(-0.5,-1.875) 10(0,-1.875) 11(0.5,-1.875) 12(1,-1.875) 20(1,1.875) 21(0.5,1.875) 22(0,1.875) 23(-0.5,1.875) 24(-1,1.875)
  silkscreen extent -2.7,-2.1 2.1,2.2, body extent -2,-2 2,2, height 1.05
"QFN32 5x5x0.85_V1.1" [mm] "Updated pads length and overlay."
  rect 0.83x0.3 smd mask+0.025: 1(-2.46,1.75) 2(-2.46,1.25) 3(-2.46,0.75) 4(-2.46,0.25) 5(-2.46,-0.25) 6(-2.46,-0.75) 7(-2.46,-1.25) 8(-2.46,-1.75) 17(2.46,-1.75) 18(2.46,-1.25) 19(2.46,-0.75) 20(2.46,-0.25) 21(2.46,0.25) 22(2.46,0.75) 23(2.46,1.25) 24(2.46,1.75)
  rect 0.3x0.83 smd mask+0.025: 9(-1.75,-2.46) 10(-1.25,-2.46) 11(-0.75,-2.46) 12(-0.25,-2.46) 13(0.25,-2.46) 14(0.75,-2.46) 15(1.25,-2.46) 16(1.75,-2.46) 25(1.75,2.46) 26(1.25,2.46) 27(0.75,2.46) 28(0.25,2.46) 29(-0.25,2.46) 30(-0.75,2.46) 31(-1.25,2.46) 32(-1.75,2.46)
  rect 3.5x3.5 smd paste-10 mask+0.025: 33(0,0)
  silkscreen extent -2.6,-2.6 2.6,2.6, body extent -2.5,-2.5 2.5,2.5, height 0.9
QFN36_6MMX6MM [mm] "Creator MM"
  rect 1x0.28 smd mask+0.025: 1(-2.8,2) 2(-2.8,1.5) 3(-2.8,1) 4(-2.8,0.5) 5(-2.8,0) 6(-2.8,-0.5) 7(-2.8,-1) 8(-2.8,-1.5) 9(-2.8,-2) 19(2.8,-2) 20(2.8,-1.5) 21(2.8,-1) 22(2.8,-0.5) 23(2.8,0) 24(2.8,0.5) 25(2.8,1) 26(2.8,1.5) 27(2.8,2)
  rect 0.28x1 smd mask+0.025: 10(-2,-2.8) 11(-1.5,-2.8) 12(-1,-2.8) 13(-0.5,-2.8) 14(0,-2.8) 15(0.5,-2.8) 16(1,-2.8) 17(1.5,-2.8) 18(2,-2.8) 28(2,2.8) 29(1.5,2.8) 30(1,2.8) 31(0.5,2.8) 32(0,2.8) 33(-0.5,2.8) 34(-1,2.8) 35(-1.5,2.8) 36(-2,2.8)
  rect 3.7x3.7 smd paste-10 mask+0.025: 37(0,0)
  silkscreen extent -3.1,-3.1 3.1,3.1, body extent -3.1,-3.1 3.1,3.1, height 0.9
QFN48_SMALL_EP_7MMX7MM [mm] "Creator MM"
  rect 0.7x0.25 smd mask+0.03: 1(-3.44,2.75) 2(-3.44,2.25) 3(-3.44,1.75) 4(-3.44,1.25) 5(-3.44,0.75) 6(-3.44,0.25) 7(-3.44,-0.25) 8(-3.44,-0.75) 9(-3.44,-1.25) 10(-3.44,-1.75) 11(-3.44,-2.25) 12(-3.44,-2.75) 25(3.44,-2.75) 26(3.44,-2.25) 27(3.44,-1.75) 28(3.44,-1.25) 29(3.44,-0.75) 30(3.44,-0.25) 31(3.44,0.25) 32(3.44,0.75) 33(3.44,1.25) 34(3.44,1.75) 35(3.44,2.25) 36(3.44,2.75)
  rect 0.25x0.7 smd mask+0.03: 13(-2.75,-3.44) 14(-2.25,-3.44) 15(-1.75,-3.44) 16(-1.25,-3.44) 17(-0.75,-3.44) 18(-0.25,-3.44) 19(0.25,-3.44) 20(0.75,-3.44) 21(1.25,-3.44) 22(1.75,-3.44) 23(2.25,-3.44) 24(2.75,-3.44) 37(2.75,3.44) 38(2.25,3.44) 39(1.75,3.44) 40(1.25,3.44) 41(0.75,3.44) 42(0.25,3.44) 43(-0.25,3.44) 44(-0.75,3.44) 45(-1.25,3.44) 46(-1.75,3.44) 47(-2.25,3.44) 48(-2.75,3.44)
  rect 3.6x3.6 smd paste-10 mask+0.025: 49(0,0)
  silkscreen extent -3.6,-3.6 3.6,3.6, body extent -3.51,-3.51 3.51,3.51, height 0.78
R0201 [mm] "Creator MM"
  rect 0.3x0.3 smd mask+0.04: 1(-0.265,0) 2(0.265,0)
  silkscreen extent -0.6,-0.3 0.6,0.3, body extent -0.3,-0.15 0.3,0.15, height 0.32
R0402 [mm]
  rect 0.5x0.6 smd: 1(-0.5,0) 2(0.5,0)
  silkscreen extent -1,-0.6 1,0.6, body extent -0.5,-0.25 0.5,0.25, height 0.4
R0805_SMALL [mm] "Creator MM"
  rect 0.6x1.3 smd paste-0.3 mask-0.3: 1(-1,0) 2(1,0)
  silkscreen extent -1.65,-1.02 1.65,1.02, body extent -1,-0.6 1,0.6, height 0.7
R1206 [mm]
  rect 0.9x1.6 smd: 1(-1.45,0) 2(1.45,0)
  silkscreen extent -2.16,-1.14 2.16,1.14, body extent -1.6,-0.8 1.6,0.8, height 0.84
"RGY (R-PVQFN-N16)" [mm] "Creator MM"
  rect 0.9x0.28 smd mask+0.06: 1(-1.95,-0.75) 8(1.95,-0.75) 9(1.95,0.75) 16(-1.95,0.75)
  rect 0.28x0.9 smd mask+0.06: 2(-1.25,-1.7) 3(-0.75,-1.7) 4(-0.25,-1.7) 5(0.25,-1.7) 6(0.75,-1.7) 7(1.25,-1.7) 10(1.25,1.7) 11(0.75,1.7) 12(0.25,1.7) 13(-0.25,1.7) 14(-0.75,1.7) 15(-1.25,1.7)
  rect 2.55x2.05 smd paste-10 mask+0.06: 17(0,0)
  silkscreen extent -2.5,-1.9 2.1,1.9, body extent -2,-1.75 2,1.75, height 0.84
SATA_VERTICAL [mm]
  round 1.3 hole 0.74: 1(0,0) 4(-3.81,0) 7(-7.62,0)
  oval 1.07x1.3 hole 0.74: 2(-1.27,1) 3(-2.54,1) 5(-5.08,1) 6(-6.35,1)
  round 2 hole 1.35: 8(2.67,0.5) 9(-10.29,0.5)
  silkscreen extent -12.51,-2.6 4.49,3.9, body extent -12.43,-2.55 4.47,3.9, height 8.43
